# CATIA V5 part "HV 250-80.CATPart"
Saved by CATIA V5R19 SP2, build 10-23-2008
Part number: HV 250-80
Bounding box of the stored display mesh (mm): x -18.951 to 18.951, y -18.952 to 18.952, z 0.053 to 229
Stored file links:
  C:\Users\Bora\Desktop\3D KATI MODEL- CATIA PART\HV serisi\HV 250\HV 250-80.CATPart
  C:\Program Files\Dassault Systemes\B19\intel_a\reffiles\standard\MetricThickPitch.txt
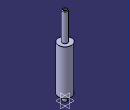
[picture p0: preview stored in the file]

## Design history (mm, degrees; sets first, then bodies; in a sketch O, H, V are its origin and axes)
Body1 (main body)
  Sketch1 on yz-plane, origin (0, 0, 0), H (0, 1, 0), V (0, 0, 1)
    point P1 (7.5, 227)
    point P3 (7.5, 227)
    point P7 (6, 17)
    point P8 (6, 1)
    point P10 (6, 1)
    point P12 (6, 17)
    line L1 (7.5, 227) -> (7.5, 148)
    arc A1 centre (5.5, 227) radius 2 from (7.5, 227) to (5.5, 229) ccw
    line L2 (6, 17) -> (6, 1)
    line L3 (5, 0) -> (6, 1)
    arc A2 centre (6, 18) radius 1 from (6, 19) to (6, 17) ccw
    line L4 (0, 0) -> (5, 0)
    line L5 (6, 19) -> (19, 19)
    line L6 (7.5, 148) -> (19, 148)
    line L7 (5.5, 229) -> (0, 229)
    point P13 (0, 229)
    line L8 (19, 148) -> (19, 19)
    horizontal: L4 H, L6 H
    tangency: L5 A2, L7 A1
    coincidence: P13 V, P1 P3, P7 P12, P8 P10
    vertical: L8 V
  Shaft1: profile Sketch1, axis Sketch1.V, angle 360
  Sketch2 on face of Shaft1 from Sketch1.L4, origin (0, 0, 0), H (1, 0, 0), V (0, -1, 0)
    point P1 (0, 0)
  Hole1: placed by Sketch2, at (0, 0, 0) direction (0, 0, 1), diameter 10.106, depth 19, threaded "M12", thread diameter 12, thread depth 19, pitch 1.75
  Sketch3 on face of Shaft1 from Sketch1.L7, origin (0, 0, 229), H (1, 0, 0), V (0, 1, 0)
    point P1 (0, 0)
  Hole2: placed by Sketch3, at (0, 0, 229) direction (0, 0, -1), diameter 6.647, depth 15, threaded "M8", thread diameter 8, thread depth 15, pitch 1.25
